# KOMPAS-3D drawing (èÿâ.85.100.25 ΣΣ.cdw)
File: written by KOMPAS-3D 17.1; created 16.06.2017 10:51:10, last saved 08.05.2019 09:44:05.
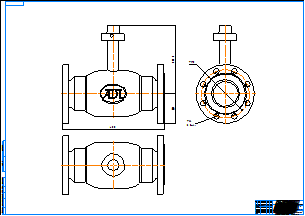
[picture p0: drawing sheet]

Sheet 1: A0, landscape

Title block, sheet 1: name: КШГ.85.100.25 фф; material: Внимание! Данный продукт является объектом авторского права ООО «Торговый Дом АДЛ». / Запрещается изменение, копирование, распространение / (в том числе путем копирования на другие сайты и ресурсы в Интернете) / или любое иное использование информации и объектов без предварительного / согласия правообладателя (ООО «Торговый Дом АДЛ»).; scale: 1:1; sheets: 1; organisation: ООО "Торговый дом АДЛ"; sheet format: A0; stored path: C:\Users\tra\Desktop\2д чертежи\Шаровые краны БИВАЛ\КШ_Бивал_серия_82_85\KOMPAS 2D\КШГ.85.100.25 фф.cdw

Views: Спереди 1, Проекционный вид 2, Проекционный вид 3
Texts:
  Klimkovich
  ADL
Dimensions and other numbers on the sheet: 400; 266,9; 115; 190; 22; 8 Отв.; 1:1; 1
